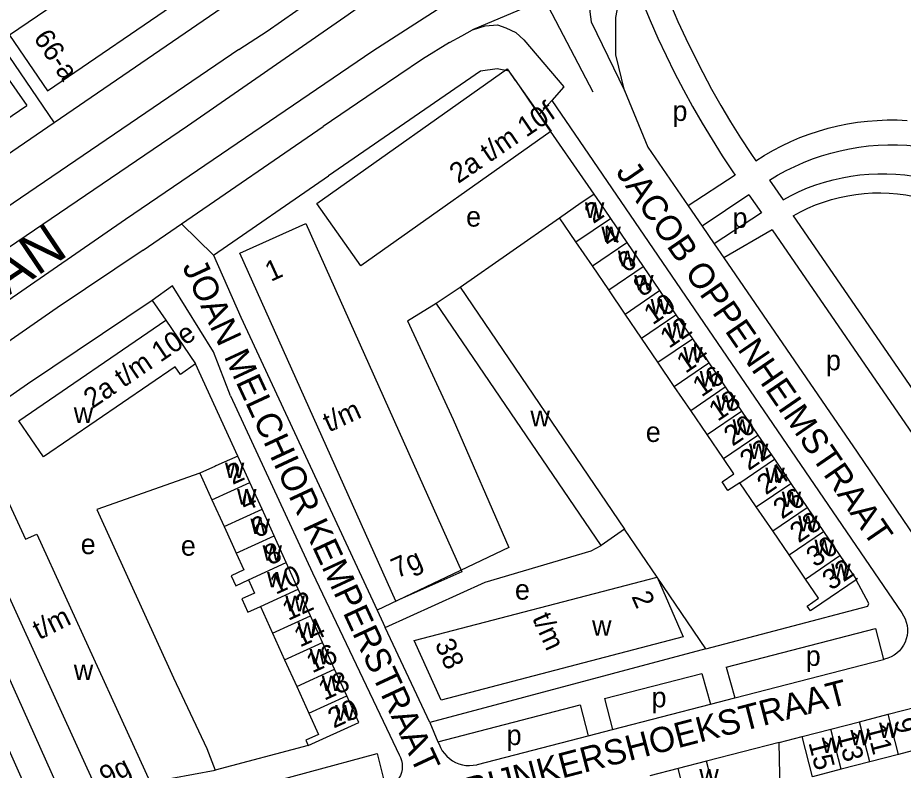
# Model space of a CAD drawing. Extents: x 157569 to 159501, y 382907 to 384670.
# Drawn here: x 158735.9 to 158911.9, y 383637.3 to 383786.7 of the extents above; entities that cross this region are included whole.
import ezdxf

# ---------------------------------------------------------------- set-up
doc = ezdxf.new("R2010")
doc.units = 0
for name, color, linetype in [('BLT_Basislijn', 7, 'Continuous'), ('BLT_Bebouwing', 7, 'Continuous'), ('BLT_Centroide', 7, 'Continuous'), ('BLT_Huisnummer', 7, 'Continuous'), ('BLT_Huisnummer_ tussenligend', 7, 'Continuous'), ('BLT_Huisnummer_reeks', 7, 'Continuous'), ('BLT_Huisnummer_zonder_bebouwing', 7, 'Continuous'), ('BLT_Onderverdeling_panden', 7, 'Continuous'), ('BLT_Plantopo', 7, 'Continuous'), ('BLT_Straatnaam', 7, 'Continuous'), ('BLT_Straatnaam_hoofdweg', 7, 'Continuous'), ('BLT_Vlakafsluiter', 7, 'Continuous')]:
    doc.layers.add(name, color=color, linetype=linetype)

msp = doc.modelspace()

# ---------------------------------------------------------------- linework, layer by layer
at = {"layer": 'BLT_Basislijn'}
for p, q in [((158840.54, 383790.43), (158850.2, 383772.05)), ((158729.04, 383786.45), (158743.12, 383765.88)), ((158849.86, 383785.93), (158856.44, 383772.3)), ((158779.78, 383780.44), (158699.57, 383725.89)), ((158839.45, 383767.42), (158850.37, 383751.72)), ((158768.38, 383745.8), (158796.59, 383765.14)), ((158774.76, 383739.57), (158797.61, 383755.33)), ((158878.46, 383755.47), (158869.12, 383749.37)), ((158885.26, 383754.47), (158888.01, 383750.6)), ((158881.18, 383751.58), (158871.89, 383745.33)), ((158881.18, 383751.58), (158883.72, 383748)), ((158869.12, 383749.37), (158871.89, 383745.33)), ((158823.77, 383733.24), (158843.56, 383747.01)), ((158883.72, 383748), (158874.3, 383741.82)), ((158889.98, 383747.4), (158934.72, 383682.26)), ((158760.76, 383740.58), (158768.38, 383745.8)), ((158774.76, 383739.57), (158768.38, 383745.8)), ((158871.89, 383745.33), (158874.3, 383741.82)), ((158885.82, 383744.63), (158876.21, 383739.03)), ((158885.82, 383744.63), (158929.6, 383680.88)), ((158874.3, 383741.82), (158876.21, 383739.03)), ((158762.58, 383730.55), (158737.83, 383713.93)), ((158762.58, 383730.55), (158765.28, 383726.64)), ((158813.31, 383726.52), (158819.06, 383730.04)), ((158779.61, 383699.68), (158771.22, 383717.96)), ((158862.94, 383675.63), (158856.47, 383685.14)), ((158872.64, 383661.36), (158862.94, 383675.63)), ((158902.53, 383675.1), (158902.43, 383675.3)), ((158807.32, 383669.04), (158808.91, 383665.59)), ((158817.78, 383646.71), (158808.91, 383665.59)), ((158876.7, 383657.74), (158906.36, 383665.41)), ((158906.36, 383665.41), (158907.93, 383659.27)), ((158872.64, 383661.36), (158817.78, 383646.71)), ((158878.41, 383651.63), (158907.93, 383659.27)), ((158907.93, 383659.27), (158908.16, 383659.33)), ((158876.7, 383657.74), (158878.41, 383651.63)), ((158852.52, 383651.49), (158871.86, 383656.49)), ((158871.86, 383656.49), (158873.57, 383650.38)), ((158819.39, 383642.92), (158847.68, 383650.23)), ((158847.68, 383650.23), (158849.22, 383644.09)), ((158852.52, 383651.49), (158854.06, 383645.34)), ((158854.06, 383645.34), (158873.57, 383650.38)), ((158873.57, 383650.38), (158878.41, 383651.63)), ((158817.78, 383646.71), (158819.39, 383642.92)), ((158849.22, 383644.09), (158854.06, 383645.34)), ((158809.85, 383644.23), (158811.69, 383640.33)), ((158819.39, 383642.92), (158819.61, 383642.42)), ((158827.24, 383638.4), (158849.22, 383644.09)), ((158887.21, 383642.78), (158891.77, 383643.94)), ((158793.61, 383642.18), (158775.09, 383637.3)), ((158887.75, 383617.55), (158887.21, 383642.78)), ((158762.21, 383634.88), (158775.09, 383637.3))]:
    msp.add_line(p, q, dxfattribs=at)
for points in [[(158821.7, 383801.57), (158800.85, 383786.86), (158769.57, 383765.2), (158713.7, 383727.23), (158696.59, 383715.73)], [(158779.78, 383780.44), (158785.47, 383784.08), (158791.11, 383788.02), (158797.01, 383792.35), (158801.6, 383796.15), (158807.82, 383802.04)], [(158855.12, 383797.57), (158853.4, 383796.43), (158851.23, 383794.3), (158850.12, 383791.96), (158849.64, 383789.47), (158849.55, 383787.92), (158849.86, 383785.93)], [(158863.28, 383795.17), (158865.61, 383789.45), (158867.1, 383786.01), (158868.67, 383782.6), (158870.3, 383779.22), (158872.01, 383775.88), (158873.79, 383772.57), (158875.64, 383769.31), (158877.56, 383766.08), (158879.55, 383762.9), (158881.6, 383759.76), (158882.57, 383758.34)], [(158701.94, 383707.7), (158717.71, 383719.47), (158757.27, 383746.75), (158806.46, 383780.17), (158827.58, 383793.81)], [(158856.44, 383772.3), (158854.72, 383779.34), (158854.72, 383786.76), (158855.42, 383790.39), (158856.82, 383792.07), (158858.64, 383793.19)], [(158858.64, 383793.19), (158861.58, 383786.16), (158863.12, 383782.68), (158864.73, 383779.23), (158866.42, 383775.82), (158868.17, 383772.44), (158870, 383769.1), (158871.9, 383765.8), (158873.87, 383762.55), (158875.9, 383759.33), (158878, 383756.16), (158878.46, 383755.47)], [(158776.5, 383788.74), (158743.12, 383765.88)], [(158821.65, 383781.79), (158824.15, 383783.15), (158826.26, 383784.34)], [(158826.26, 383784.34), (158828.76, 383785.1), (158831.21, 383785.32), (158832.89, 383784.72), (158834.85, 383783.8), (158836.48, 383782.33), (158844.41, 383772.99), (158842, 383770.28)], [(158821.65, 383781.79), (158816.34, 383778.54), (158806.89, 383772.18), (158796.59, 383765.14)], [(158834.78, 383774.27), (158833.54, 383776.11), (158831.14, 383776.59), (158827.85, 383776.12), (158797.61, 383755.33)], [(158856.44, 383772.3), (158861.13, 383761.02), (158869.12, 383749.37)], [(158842, 383770.28), (158839.45, 383767.42)], [(158842, 383770.28), (158911.56, 383668.52)], [(158882.57, 383758.34), (158884.24, 383759.39), (158885.95, 383760.38), (158887.71, 383761.3), (158889.5, 383762.15), (158891.32, 383762.92), (158893.17, 383763.62), (158895.05, 383764.24), (158896.95, 383764.79), (158898.88, 383765.26), (158900.82, 383765.65), (158902.77, 383765.97), (158904.74, 383766.2), (158906.71, 383766.36), (158908.69, 383766.43), (158910.67, 383766.43), (158912.65, 383766.34)], [(158743.12, 383765.88), (158694.82, 383732.81), (158691.75, 383732.4), (158689.15, 383734.61)], [(158885.26, 383754.47), (158886.9, 383755.45), (158888.58, 383756.37), (158890.3, 383757.21), (158892.05, 383757.98), (158893.82, 383758.68), (158895.63, 383759.31), (158897.46, 383759.85), (158899.32, 383760.33), (158901.19, 383760.72), (158903.07, 383761.03), (158904.97, 383761.27), (158906.88, 383761.42), (158908.79, 383761.5), (158910.7, 383761.49), (158912.61, 383761.41), (158914.51, 383761.24), (158916.41, 383761), (158918.3, 383760.68), (158920.16, 383760.27), (158922.02, 383759.79), (158923.84, 383759.24), (158925.65, 383758.61), (158927.22, 383757.98)], [(158888.01, 383750.6), (158889.59, 383751.44), (158891.2, 383752.22), (158892.85, 383752.92), (158894.53, 383753.54), (158896.24, 383754.09), (158897.96, 383754.57), (158899.71, 383754.96), (158901.47, 383755.28), (158903.25, 383755.52), (158905.03, 383755.68), (158906.82, 383755.76), (158908.61, 383755.76), (158910.4, 383755.68), (158912.18, 383755.52), (158913.96, 383755.28), (158915.72, 383754.96), (158917.47, 383754.56), (158919.2, 383754.09), (158920.9, 383753.54), (158922.58, 383752.91), (158924.23, 383752.21), (158924.88, 383751.91)], [(158889.98, 383747.4), (158891.44, 383748.19), (158892.93, 383748.91), (158894.46, 383749.56), (158896.02, 383750.13), (158897.6, 383750.62), (158899.21, 383751.04), (158900.83, 383751.38), (158902.47, 383751.65), (158904.12, 383751.83), (158905.77, 383751.93), (158907.43, 383751.96), (158909.09, 383751.9), (158910.74, 383751.76), (158912.39, 383751.55), (158914.02, 383751.25), (158915.63, 383750.88), (158917.23, 383750.43), (158918.8, 383749.9), (158920.35, 383749.3), (158921.86, 383748.62), (158923.34, 383747.87), (158924.74, 383747.08)], [(158760.76, 383740.58), (158743.71, 383729.14), (158726.02, 383716.86), (158719.15, 383711.86), (158710.83, 383704.58), (158702.74, 383697.25)], [(158774.76, 383739.57), (158780.19, 383727.24), (158807.32, 383669.04)], [(158876.21, 383739.03), (158902.69, 383700.43), (158918.06, 383677.77)], [(158778.18, 383711.62), (158774.75, 383720.39), (158766.63, 383733.51), (158762.58, 383730.55)], [(158813.31, 383726.52), (158822.39, 383706.91), (158833.46, 383681.49), (158807.32, 383669.04)], [(158737.83, 383713.93), (158715.02, 383698.14)], [(158778.18, 383711.62), (158794.48, 383676.48), (158809.85, 383644.23)], [(158715.02, 383698.14), (158745.8, 383629.49), (158752.9, 383630.63)], [(158772.06, 383696.25), (158751.58, 383689.04), (158766.85, 383655.59), (158773.43, 383641.6), (158775.09, 383637.3)], [(158710.51, 383695.02), (158713.43, 383687.6), (158741.59, 383624.49)], [(158808.91, 383665.59), (158828.75, 383674.6), (158849.83, 383680.85), (158851.8, 383681.89)], [(158872.64, 383661.36), (158904.84, 383669.84), (158905.03, 383670.35), (158902.53, 383675.1)], [(158911.56, 383668.52), (158911.93, 383667.95), (158912.24, 383667.34), (158912.48, 383666.7), (158912.63, 383666.04), (158912.71, 383665.36), (158912.71, 383664.68), (158912.63, 383664), (158912.47, 383663.33), (158912.24, 383662.69), (158911.93, 383662.08), (158911.55, 383661.51), (158911.11, 383660.99), (158910.61, 383660.53), (158910.06, 383660.12), (158909.46, 383659.79), (158908.83, 383659.52), (158908.16, 383659.33)], [(158819.61, 383642.42), (158819.89, 383641.76), (158820.24, 383641.14), (158820.66, 383640.56), (158821.14, 383640.03), (158821.68, 383639.56), (158822.27, 383639.15), (158822.9, 383638.81), (158823.56, 383638.54), (158824.25, 383638.35), (158824.96, 383638.23), (158825.68, 383638.2), (158826.39, 383638.24), (158827.1, 383638.36), (158827.24, 383638.4)], [(158779.9, 383633.15), (158807.28, 383640.6), (158809.04, 383633.69)], [(158811.69, 383640.33), (158811.95, 383639.78), (158812.14, 383639.21), (158812.25, 383638.61), (158812.29, 383638.01), (158812.24, 383637.41), (158812.11, 383636.81), (158811.91, 383636.24), (158811.63, 383635.71), (158811.29, 383635.21), (158810.88, 383634.76), (158810.42, 383634.37), (158809.91, 383634.05), (158809.36, 383633.79), (158809.04, 383633.69)]]:
    msp.add_lwpolyline(points, dxfattribs=at)
at = {"layer": 'BLT_Bebouwing'}
for p, q in [((158834.78, 383774.27), (158839.45, 383767.42)), ((158716.95, 383755.48), (158737.7, 383769.29)), ((158846.82, 383742.23), (158843.56, 383747.01)), ((158853.66, 383746.89), (158856.92, 383742.1)), ((158850.08, 383737.44), (158846.82, 383742.23)), ((158856.92, 383742.1), (158860.18, 383737.32)), ((158853.34, 383732.66), (158850.08, 383737.44)), ((158860.18, 383737.32), (158863.44, 383732.53)), ((158819.06, 383730.04), (158823.77, 383733.24)), ((158823.77, 383733.24), (158856.47, 383685.14)), ((158856.59, 383727.87), (158853.34, 383732.66)), ((158863.44, 383732.53), (158866.7, 383727.75)), ((158851.8, 383681.89), (158819.06, 383730.04)), ((158859.85, 383723.09), (158856.59, 383727.87)), ((158866.7, 383727.75), (158869.96, 383722.96)), ((158736.07, 383706.67), (158765.28, 383726.64)), ((158765.28, 383726.64), (158771.22, 383717.96)), ((158863.11, 383718.3), (158859.85, 383723.09)), ((158869.96, 383722.96), (158873.22, 383718.18)), ((158767.18, 383717.38), (158741.01, 383699.49)), ((158768.19, 383715.9), (158767.18, 383717.38)), ((158771.22, 383717.96), (158768.19, 383715.9)), ((158866.37, 383713.52), (158863.11, 383718.3)), ((158873.22, 383718.18), (158876.48, 383713.39)), ((158869.63, 383708.73), (158866.37, 383713.52)), ((158876.48, 383713.39), (158879.74, 383708.61)), ((158872.89, 383703.95), (158869.63, 383708.73)), ((158879.74, 383708.61), (158882.99, 383703.82)), ((158741.01, 383699.49), (158736.07, 383706.67)), ((158876.15, 383699.16), (158872.89, 383703.95)), ((158882.99, 383703.82), (158886.25, 383699.04)), ((158729.41, 383700.35), (158737.42, 383683.13)), ((158782.01, 383694.39), (158779.61, 383699.68)), ((158886.25, 383699.04), (158889.51, 383694.25)), ((158784.42, 383689.1), (158782.01, 383694.39)), ((158882.67, 383689.59), (158879.41, 383694.38)), ((158889.51, 383694.25), (158892.77, 383689.47)), ((158774.47, 383690.96), (158776.88, 383685.67)), ((158786.82, 383683.8), (158784.42, 383689.1)), ((158885.92, 383684.8), (158882.67, 383689.59)), ((158892.77, 383689.47), (158896.03, 383684.68)), ((158856.47, 383685.14), (158851.8, 383681.89)), ((158737.42, 383683.13), (158739.67, 383684.17)), ((158739.67, 383684.17), (158762.21, 383634.88)), ((158789.23, 383678.51), (158786.82, 383683.8)), ((158889.18, 383680.02), (158885.92, 383684.8)), ((158896.03, 383684.68), (158899.29, 383679.9)), ((158892.44, 383675.24), (158889.18, 383680.02)), ((158899.29, 383679.9), (158902.43, 383675.3)), ((158752.9, 383630.63), (158730.69, 383679.26)), ((158791.63, 383673.22), (158789.23, 383678.51)), ((158794.04, 383667.92), (158791.63, 383673.22)), ((158796.45, 383662.63), (158794.04, 383667.92)), ((158786.5, 383664.5), (158788.9, 383659.2)), ((158798.85, 383657.34), (158796.45, 383662.63)), ((158788.9, 383659.2), (158791.31, 383653.91)), ((158801.26, 383652.04), (158798.85, 383657.34)), ((158791.31, 383653.91), (158793.71, 383648.62)), ((158903.17, 383646.9), (158908.87, 383648.38)), ((158908.87, 383648.38), (158914.57, 383649.86)), ((158897.47, 383645.42), (158903.17, 383646.9)), ((158891.77, 383643.94), (158897.47, 383645.42)), ((158910.94, 383640.41), (158905.24, 383638.93)), ((158867.14, 383637.6), (158861.5, 383636.12)), ((158872.77, 383639.07), (158867.14, 383637.6)), ((158875.56, 383628.4), (158872.77, 383639.07)), ((158905.24, 383638.93), (158899.54, 383637.46))]:
    msp.add_line(p, q, dxfattribs=at)
for points in [[(158741.76, 383772.22), (158769.15, 383790.93), (158761.63, 383801.95), (158734.24, 383783.28), (158741.76, 383772.22)], [(158704.47, 383784.59), (158719.71, 383795.03), (158737.7, 383769.29)], [(158843.56, 383747.01), (158846.25, 383748.89), (158847.88, 383750.02), (158850.37, 383751.72)], [(158850.37, 383751.72), (158851.55, 383750), (158853.66, 383746.89)], [(158779.61, 383699.68), (158775.26, 383697.71), (158775.03, 383697.6), (158774.6, 383697.41), (158772.06, 383696.25)], [(158879.41, 383694.38), (158877.03, 383692.86), (158875.88, 383694.56), (158878.2, 383696.14), (158876.15, 383699.16)], [(158772.06, 383696.25), (158774.47, 383690.96)], [(158776.88, 383685.67), (158778.47, 383682.16), (158779.28, 383680.38)], [(158779.28, 383680.38), (158780.8, 383677.04), (158778.29, 383675.9), (158779.19, 383673.92), (158781.71, 383675.06)], [(158781.71, 383675.06), (158782.9, 383672.43), (158780.39, 383671.28), (158781.58, 383668.65), (158784.09, 383669.79)], [(158862.94, 383675.63), (158868.15, 383663.78), (158820.02, 383651.2), (158814.64, 383663.04), (158862.94, 383675.63)], [(158902.53, 383675.1), (158895.7, 383670.45), (158893.43, 383668.9), (158892.76, 383669.88), (158895.03, 383671.43), (158892.44, 383675.24)], [(158902.43, 383675.3), (158902.61, 383675.42), (158902.73, 383675.24), (158902.53, 383675.1)], [(158784.09, 383669.79), (158786.5, 383664.5)], [(158793.61, 383642.18), (158803.66, 383646.74), (158801.26, 383652.04)], [(158793.71, 383648.62), (158795.63, 383644.39), (158793.13, 383643.25), (158793.61, 383642.18)], [(158899.54, 383637.46), (158893.83, 383635.98), (158891.77, 383643.94)], [(158916.64, 383641.89), (158910.94, 383640.41)]]:
    msp.add_lwpolyline(points, dxfattribs=at)
at = {"layer": 'BLT_Onderverdeling_panden'}
for p, q in [((158846.82, 383742.23), (158853.66, 383746.89)), ((158850.08, 383737.44), (158856.92, 383742.1)), ((158853.34, 383732.66), (158860.18, 383737.32)), ((158856.59, 383727.87), (158863.44, 383732.53)), ((158859.85, 383723.09), (158866.7, 383727.75)), ((158863.11, 383718.3), (158869.96, 383722.96)), ((158866.37, 383713.52), (158873.22, 383718.18)), ((158869.63, 383708.73), (158876.48, 383713.39)), ((158872.89, 383703.95), (158879.74, 383708.61)), ((158876.15, 383699.16), (158882.99, 383703.82)), ((158879.41, 383694.38), (158886.25, 383699.04)), ((158774.47, 383690.96), (158782.01, 383694.39)), ((158882.67, 383689.59), (158889.51, 383694.25)), ((158776.88, 383685.67), (158784.42, 383689.1)), ((158885.92, 383684.8), (158892.77, 383689.47)), ((158779.28, 383680.38), (158786.82, 383683.8)), ((158889.18, 383680.02), (158896.03, 383684.68)), ((158892.44, 383675.24), (158899.29, 383679.9)), ((158781.71, 383675.06), (158789.23, 383678.51)), ((158784.09, 383669.79), (158791.63, 383673.22)), ((158786.5, 383664.5), (158794.04, 383667.92)), ((158788.9, 383659.2), (158796.45, 383662.63)), ((158791.31, 383653.91), (158798.85, 383657.34)), ((158793.71, 383648.62), (158801.26, 383652.04)), ((158910.94, 383640.41), (158908.87, 383648.38)), ((158905.24, 383638.93), (158903.17, 383646.9)), ((158899.54, 383637.46), (158897.47, 383645.42)), ((158869.23, 383629.59), (158867.14, 383637.6))]:
    msp.add_line(p, q, dxfattribs=at)
at = {"layer": 'BLT_Plantopo'}
for points in [[(158795.3, 383749.86), (158833.14, 383776.62), (158841.9, 383764.23), (158804.06, 383737.47)], [(158793.13, 383745.86), (158824.1, 383676.7), (158811, 383670.83), (158780.03, 383739.99)]]:
    msp.add_lwpolyline(points, close=True, dxfattribs=at)
at = {"layer": 'BLT_Vlakafsluiter'}
for p, q in [((158840.54, 383790.43), (158826.26, 383784.34)), ((158887.21, 383642.78), (158872.77, 383639.07))]:
    msp.add_line(p, q, dxfattribs=at)

# ---------------------------------------------------------------- texts
at = {"layer": 'BLT_Centroide'}
for s, p in [('p', (158866.01, 383766.24)), ('w', (158848.59, 383746.97)), ('e', (158824.98, 383745.25)), ('p', (158877.94, 383745.01)), ('w', (158851.87, 383742.16)), ('w', (158855.13, 383737.38)), ('w', (158858.39, 383732.59)), ('w', (158861.65, 383727.81)), ('w', (158864.91, 383723.03)), ('w', (158868.16, 383718.25)), ('p', (158896.51, 383716.71)), ('w', (158871.42, 383713.47)), ('w', (158874.68, 383708.66)), ('w', (158747, 383706.25)), ('w', (158837.77, 383705.59)), ('w', (158877.94, 383703.88)), ('e', (158860.7, 383702.47)), ('w', (158881.2, 383699.09)), ('w', (158777.04, 383695.31)), ('w', (158884.46, 383694.31)), ('w', (158779.45, 383690.03)), ('w', (158887.72, 383689.53)), ('w', (158782.12, 383684.16)), ('w', (158890.98, 383684.75)), ('e', (158748.38, 383680.19)), ('e', (158768.29, 383679.88)), ('w', (158784.52, 383678.88)), ('w', (158894.23, 383679.97)), ('w', (158897.56, 383675.19)), ('w', (158785.41, 383673.56)), ('e', (158834.69, 383671.15)), ('w', (158789.06, 383668.84)), ('w', (158791.47, 383663.56)), ('w', (158850.02, 383663.97)), ('w', (158793.88, 383658.28)), ('p', (158892.5, 383657.99)), ('w', (158747, 383655.17)), ('w', (158796.28, 383652.97)), ('p', (158861.85, 383649.76)), ('w', (158798.95, 383647.12)), ('w', (158907.06, 383643.66)), ('p', (158833.04, 383642.26)), ('w', (158901.36, 383642.19)), ('w', (158895.66, 383640.69)), ('w', (158871.34, 383634.42))]:
    msp.add_text(s, height=4, dxfattribs=at).set_placement(p)
at = {"layer": 'BLT_Huisnummer'}
for s, rotation, p in [('2', 34.256, (158850.27, 383745.72)), ('6', 34.256, (158856.77, 383735.93)), ('10', 34.256, (158862.07, 383725.61)), ('14', 34.256, (158868.59, 383715.99)), ('18', 34.256, (158874.98, 383706.44)), ('22', 34.256, (158881.14, 383696.67)), ('2', 24.4365, (158778.56, 383693.9)), ('26', 34.256, (158887.77, 383687.03)), ('6', 24.4365, (158783.34, 383683.28)), ('32', 34.256, (158897.53, 383672.87)), ('10', 24.4365, (158787.14, 383672.09)), ('14', 24.4365, (158791.94, 383661.62)), ('20', 24.4365, (158798.66, 383645.52)), ('9', 284.5394, (158910.01, 383647.13)), ('15', 284.5394, (158893, 383642.74))]:
    msp.add_text(s, height=4, rotation=rotation, dxfattribs=at).set_placement(p)
at = {"layer": 'BLT_Huisnummer_ tussenligend'}
for s, rotation, p in [('4', 34.256, (158853.45, 383740.93)), ('8', 34.256, (158859.99, 383731.17)), ('12', 34.256, (158865.3, 383720.94)), ('16', 34.256, (158871.77, 383711.29)), ('20', 34.256, (158877.95, 383701.51)), ('24', 34.256, (158884.56, 383691.84)), ('4', 24.4365, (158781.05, 383688.58)), ('28', 34.256, (158891.09, 383682.29)), ('30', 34.256, (158894.34, 383677.46)), ('8', 24.4365, (158785.98, 383677.9)), ('12', 24.4365, (158789.61, 383666.9)), ('16', 24.4365, (158794.39, 383656.48)), ('18', 24.4365, (158796.79, 383651.04)), ('13', 284.5394, (158898.75, 383644.41)), ('11', 284.5394, (158904.46, 383645.86))]:
    msp.add_text(s, height=4, rotation=rotation, dxfattribs=at).set_placement(p)
at = {"layer": 'BLT_Huisnummer_reeks'}
for s, rotation, p in [('66-a', 304.2499, (158738.86, 383782.72)), ('2', 294.1015, (158857.78, 383671.8)), ('t/m', 294.1015, (158838.06, 383667.5)), ('38', 294.1015, (158818.69, 383662.35))]:
    msp.add_text(s, height=4, rotation=rotation, dxfattribs=at).set_placement(p)
at = {"layer": 'BLT_Huisnummer_zonder_bebouwing'}
for s, rotation, p in [('2a t/m 10f', 34.256, (158823.41, 383753.69)), ('1', 24.4365, (158786.16, 383734.24)), ('2a t/m 10e', 34.256, (158750.69, 383708.98)), ('t/m', 24.4365, (158797.7, 383704.34)), ('7g', 24.4365, (158811.23, 383675.33)), ('t/m', 26.4365, (158740.11, 383663.1)), ('9g', 26.4365, (158753.38, 383634))]:
    msp.add_text(s, height=4, rotation=rotation, dxfattribs=at).set_placement(p)
at = {"layer": 'BLT_Straatnaam'}
for s, height, rotation, p in [('JACOB OPPENHEIMSTRAAT', 4.9999, 304.4896, (158854.62, 383756.09)), ('JOAN MELCHIOR KEMPERSTRAAT', 5, 294.9253, (158768.48, 383737.31)), ('CORNELIS VAN BIJNKERSHOEKSTRAAT', 4.9999, 14.6494, (158775.77, 383617.75))]:
    msp.add_text(s, height=height, rotation=rotation, dxfattribs=at).set_placement(p)
at = {"layer": 'BLT_Straatnaam_hoofdweg'}
msp.add_text('NOORD BRABANTLAAN', height=8, rotation=34.0328, dxfattribs=at).set_placement((158645.65, 383671.81))

doc.saveas('drawing.dxf')
